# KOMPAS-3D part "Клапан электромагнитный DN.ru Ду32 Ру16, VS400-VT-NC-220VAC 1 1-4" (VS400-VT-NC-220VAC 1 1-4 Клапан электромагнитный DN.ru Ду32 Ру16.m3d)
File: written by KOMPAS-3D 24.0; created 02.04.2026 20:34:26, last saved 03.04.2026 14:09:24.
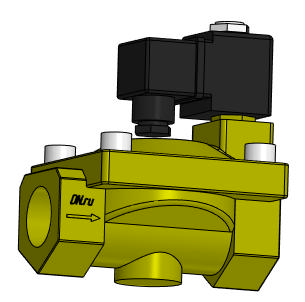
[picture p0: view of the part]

Document properties: Автор: artio; Полное имя файла: C:\Users\artio\OneDrive\Рабочий стол\Клапан электромагнитный DN.ru\VS400-VT-NC\VS400-VT-NC-220VAC 1 1-4 Клапан электромагнитный DN.ru Ду32 Ру16.m3d

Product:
- Body: Тело 1  | qty 1
    Масса: 4.144257
- Part/product: Клапан электромагнитный DN.ru Ду32 Ру16  | designation VS400-VT-NC-220VAC 1 1-4
    Масса: 2.569
    Раздел спецификации: Прочие изделия
    Примечание: D130-04701
    additional columns: ef56311e-7521-43dc-8291-0e6108b3d81d; VS400-ET-NC-220VAC 1 1-4; artio; c; Шероховатость не задана; Да

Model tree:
1. Операция без истории:1

Expressions: VS400-VT-NC-220VAC 1 1-4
